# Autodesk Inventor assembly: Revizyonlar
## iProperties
Created: 2004-11
Part Number: Revizyonlar
Cost Center: 0 lbmass
Document SubType Name: Assembly
Designer: busseym
Manufacturer: Standard
Standards Organization: Custom
Description: SWING ARM, LCD FLAT PANEL
Stock Number: SA-LCD-17
Dept. ID: Product Design
Description #2: ---
Finish #1: ---
Finish #2: ---
Material ID: ---
Project Number: ---
Author: busseym
